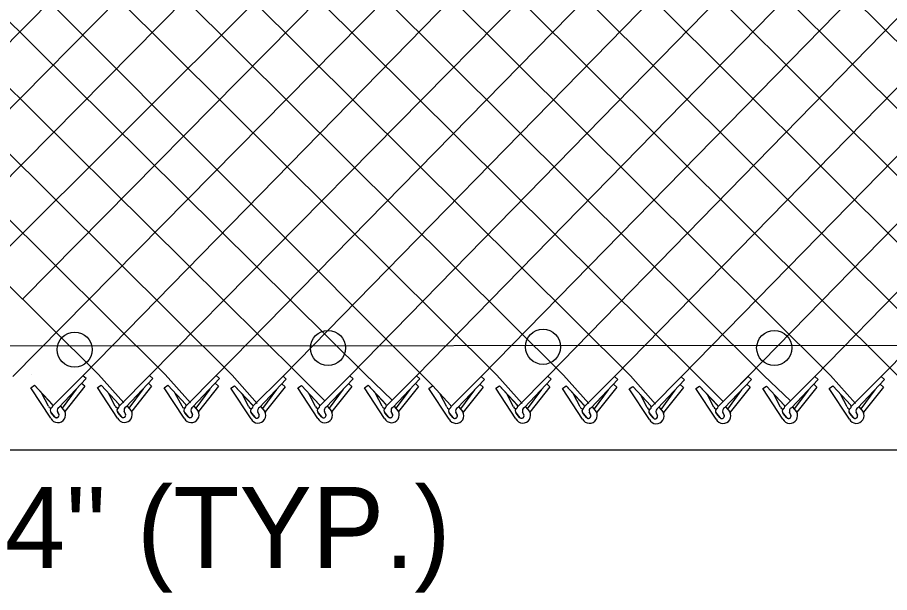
# Model space of a CAD drawing. Extents: x 0 to 1270, y 0 to 830.
# Drawn here: x 867.2 to 919.9, y 369.2 to 403.9 of the extents above; entities that cross this region are included whole.
import ezdxf

# ---------------------------------------------------------------- set-up
doc = ezdxf.new("R2010")
doc.units = 0
for name, color, linetype in [('CT_Dimensions', 7, 'Continuous'), ('sb_Chainlink Fence', 7, 'Continuous'), ('sb_Existing Structural Steel', 7, 'Continuous')]:
    doc.layers.add(name, color=color, linetype=linetype)

msp = doc.modelspace()

# ---------------------------------------------------------------- linework, layer by layer
at = {"layer": 'sb_Chainlink Fence'}
for p, q in [((816.414, 437.549), (872.125, 382.342)), ((836.532, 437.583), (892.288, 381.648)), ((840.607, 437.539), (896.164, 382.299)), ((844.66, 437.516), (900.191, 382.291)), ((848.65, 437.556), (904.222, 382.261)), ((852.704, 437.533), (908.25, 382.284)), ((856.741, 437.527), (912.277, 382.287)), ((860.842, 437.456), (916.291, 382.289)), ((865.54, 388.877), (914.406, 437.633)), ((850.828, 382.233), (904.801, 436.901)), ((915.349, 382.223), (968.936, 437.129)), ((866.942, 382.227), (920.625, 436.62)), ((867.562, 386.914), (916.354, 436.35)), ((871.171, 382.269), (924.083, 436.377)), ((874.065, 436.515), (928.376, 382.261)), ((879.224, 382.271), (932.156, 436.339)), ((883.256, 382.241), (936.183, 436.368)), ((887.284, 382.263), (940.214, 436.419)), ((891.31, 382.266), (944.243, 436.417)), ((895.209, 382.226), (948.269, 436.435)), ((899.236, 382.236), (952.075, 436.386)), ((903.263, 382.228), (956.31, 436.464)), ((907.294, 382.198), (960.337, 436.493)), ((910.415, 381.309), (964.368, 436.544)), ((919.363, 382.226), (972.423, 436.56)), ((846.789, 382.209), (900.235, 436.295)), ((854.855, 382.243), (908.301, 436.31)), ((822.448, 435.621), (876.152, 382.334)), ((826.475, 435.629), (880.184, 382.304)), ((834.503, 435.602), (888.238, 382.33)), ((866.918, 435.53), (920.318, 382.299)), ((870.946, 435.558), (924.345, 382.291)), ((879.005, 435.607), (932.405, 382.284)), ((883.031, 435.625), (936.431, 382.287)), ((887.046, 435.644), (940.47, 382.31)), ((875.197, 382.279), (926.633, 434.462)), ((832.366, 433.688), (884.212, 382.327)), ((868.099, 382.332), (868.099, 382.332)), ((869.357, 380.447), (871.171, 382.269)), ((871.368, 382.089), (871.171, 382.269)), ((872.125, 382.342), (873.643, 380.634)), ((873.384, 380.458), (875.197, 382.279)), ((875.395, 382.1), (875.197, 382.279)), ((876.152, 382.334), (877.67, 380.625)), ((877.411, 380.449), (879.224, 382.271)), ((879.422, 382.091), (879.224, 382.271)), ((880.184, 382.304), (881.701, 380.596)), ((881.442, 380.419), (883.256, 382.241)), ((883.454, 382.062), (883.256, 382.241)), ((884.212, 382.327), (885.783, 380.759)), ((885.47, 380.442), (887.284, 382.263)), ((887.482, 382.084), (887.284, 382.263)), ((888.238, 382.33), (889.844, 380.795)), ((889.497, 380.445), (891.31, 382.266)), ((891.508, 382.087), (891.31, 382.266)), ((893.395, 380.404), (895.209, 382.226)), ((895.407, 382.046), (895.209, 382.226)), ((896.164, 382.299), (897.681, 380.591)), ((897.422, 380.414), (899.236, 382.236)), ((899.433, 382.057), (899.236, 382.236)), ((900.191, 382.291), (901.708, 380.582)), ((901.449, 380.406), (903.263, 382.228)), ((903.461, 382.048), (903.263, 382.228)), ((904.222, 382.261), (905.74, 380.552)), ((905.48, 380.376), (907.294, 382.198)), ((907.492, 382.018), (907.294, 382.198)), ((908.25, 382.284), (909.821, 380.716)), ((909.509, 380.399), (911.322, 382.22)), ((911.52, 382.041), (911.322, 382.22)), ((912.277, 382.287), (913.882, 380.752)), ((913.535, 380.402), (915.349, 382.223)), ((915.547, 382.044), (915.349, 382.223)), ((916.291, 382.289), (917.809, 380.58)), ((917.55, 380.404), (919.363, 382.226)), ((919.561, 382.046), (919.363, 382.226)), ((868.027, 381.538), (868.25, 381.691)), ((868.25, 381.691), (869.328, 380.529)), ((868.25, 381.691), (869.334, 380.522)), ((869.756, 380.376), (871.368, 382.089)), ((871.301, 381.626), (870.095, 380.109)), ((871.301, 381.626), (871.103, 381.806)), ((872.053, 381.549), (872.276, 381.701)), ((872.276, 381.701), (873.354, 380.539)), ((872.276, 381.701), (873.361, 380.532)), ((873.782, 380.386), (875.395, 382.1)), ((875.328, 381.637), (874.122, 380.119)), ((875.328, 381.637), (875.13, 381.816)), ((876.08, 381.54), (876.303, 381.693)), ((876.303, 381.693), (877.381, 380.531)), ((876.303, 381.693), (877.388, 380.524)), ((877.81, 380.378), (879.422, 382.091)), ((879.355, 381.628), (878.149, 380.111)), ((879.355, 381.628), (879.157, 381.808)), ((880.112, 381.511), (880.335, 381.663)), ((880.335, 381.663), (881.413, 380.501)), ((880.335, 381.663), (881.42, 380.494)), ((881.841, 380.348), (883.454, 382.062)), ((883.386, 381.599), (882.18, 380.081)), ((883.386, 381.599), (883.188, 381.778)), ((884.14, 381.533), (884.363, 381.685)), ((884.363, 381.685), (885.441, 380.523)), ((884.363, 381.685), (885.448, 380.517)), ((885.869, 380.371), (887.482, 382.084)), ((887.415, 381.621), (886.208, 380.104)), ((887.415, 381.621), (887.217, 381.8)), ((888.166, 381.536), (888.389, 381.688)), ((888.389, 381.688), (889.467, 380.526)), ((888.389, 381.688), (889.474, 380.519)), ((889.896, 380.373), (891.508, 382.087)), ((891.441, 381.624), (890.235, 380.106)), ((891.441, 381.624), (891.243, 381.803)), ((892.062, 381.503), (892.285, 381.656)), ((892.288, 381.648), (893.366, 380.486)), ((892.288, 381.648), (893.373, 380.479)), ((893.794, 380.333), (895.407, 382.046)), ((895.34, 381.583), (895.142, 381.763)), ((896.092, 381.506), (896.315, 381.658)), ((896.315, 381.658), (897.393, 380.496)), ((896.315, 381.658), (897.399, 380.489)), ((897.821, 380.343), (899.433, 382.057)), ((899.366, 381.594), (898.16, 380.076)), ((899.366, 381.594), (899.168, 381.773)), ((900.119, 381.497), (900.342, 381.65)), ((900.342, 381.65), (901.42, 380.488)), ((900.342, 381.65), (901.427, 380.481)), ((901.848, 380.335), (903.461, 382.048)), ((903.393, 381.585), (903.196, 381.765)), ((904.15, 381.467), (904.373, 381.62)), ((904.373, 381.62), (905.451, 380.458)), ((904.373, 381.62), (905.458, 380.451)), ((905.879, 380.305), (907.492, 382.018)), ((907.425, 381.555), (907.227, 381.735)), ((908.178, 381.49), (908.401, 381.642)), ((908.401, 381.642), (909.479, 380.48)), ((908.401, 381.642), (909.486, 380.474)), ((909.907, 380.328), (911.52, 382.041)), ((911.453, 381.578), (911.255, 381.757)), ((912.205, 381.493), (912.428, 381.645)), ((912.428, 381.645), (913.506, 380.483)), ((912.428, 381.645), (913.513, 380.476)), ((913.934, 380.33), (915.547, 382.044)), ((915.479, 381.581), (915.282, 381.76)), ((916.219, 381.495), (916.442, 381.648)), ((916.442, 381.648), (917.52, 380.486)), ((916.442, 381.648), (917.527, 380.479)), ((917.948, 380.333), (919.561, 382.046)), ((919.494, 381.583), (919.296, 381.763)), ((869.245, 379.694), (868.027, 381.538)), ((869.106, 380.422), (868.7, 381.198)), ((870.782, 381.46), (869.933, 380.305)), ((873.272, 379.704), (872.053, 381.549)), ((873.133, 380.432), (872.727, 381.208)), ((874.809, 381.471), (873.96, 380.316)), ((877.299, 379.696), (876.08, 381.54)), ((877.16, 380.424), (876.754, 381.199)), ((878.836, 381.462), (877.987, 380.307)), ((881.33, 379.666), (880.112, 381.511)), ((881.191, 380.394), (880.785, 381.17)), ((882.867, 381.432), (882.018, 380.278)), ((885.358, 379.688), (884.14, 381.533)), ((885.22, 380.416), (884.814, 381.192)), ((886.895, 381.455), (886.047, 380.3)), ((889.385, 379.691), (888.166, 381.536)), ((889.246, 380.419), (888.84, 381.195)), ((890.922, 381.458), (890.073, 380.303)), ((893.283, 379.651), (892.065, 381.495)), ((893.144, 380.379), (892.739, 381.154)), ((894.82, 381.417), (893.972, 380.262)), ((895.34, 381.583), (894.133, 380.066)), ((897.31, 379.661), (896.092, 381.506)), ((897.171, 380.389), (896.765, 381.165)), ((898.847, 381.428), (897.998, 380.273)), ((901.337, 379.653), (900.119, 381.497)), ((901.198, 380.381), (900.792, 381.156)), ((902.874, 381.419), (902.025, 380.264)), ((903.393, 381.585), (902.187, 380.068)), ((905.368, 379.623), (904.15, 381.467)), ((905.229, 380.351), (904.824, 381.127)), ((906.905, 381.389), (906.057, 380.234)), ((907.425, 381.555), (906.218, 380.038)), ((909.396, 379.645), (908.178, 381.49)), ((909.258, 380.373), (908.852, 381.149)), ((910.934, 381.412), (910.085, 380.257)), ((911.453, 381.578), (910.247, 380.06)), ((913.423, 379.648), (912.205, 381.493)), ((913.284, 380.376), (912.878, 381.152)), ((914.96, 381.415), (914.111, 380.26)), ((915.479, 381.581), (914.273, 380.063)), ((917.437, 379.651), (916.219, 381.495)), ((917.299, 380.379), (916.893, 381.154)), ((918.974, 381.417), (918.126, 380.262)), ((919.494, 381.583), (918.288, 380.066)), ((869.471, 379.786), (869.269, 380.028)), ((869.269, 380.028), (869.491, 379.765)), ((869.732, 379.929), (869.65, 380.106)), ((869.65, 380.1), (869.731, 379.933)), ((869.823, 380.424), (870.071, 380.131)), ((869.827, 380.419), (870.072, 380.13)), ((870.071, 380.131), (870.089, 380.097)), ((870.089, 380.097), (870.105, 380.06)), ((873.497, 379.797), (873.295, 380.039)), ((873.295, 380.039), (873.518, 379.775)), ((873.758, 379.939), (873.677, 380.117)), ((873.677, 380.11), (873.758, 379.943)), ((873.85, 380.434), (874.098, 380.141)), ((873.853, 380.43), (874.099, 380.14)), ((874.098, 380.141), (874.116, 380.107)), ((874.116, 380.107), (874.131, 380.071)), ((877.524, 379.788), (877.322, 380.03)), ((877.322, 380.03), (877.545, 379.767)), ((877.786, 379.931), (877.704, 380.108)), ((877.704, 380.102), (877.785, 379.935)), ((877.877, 380.426), (878.125, 380.133)), ((877.88, 380.421), (878.126, 380.132)), ((878.125, 380.133), (878.143, 380.099)), ((878.143, 380.099), (878.159, 380.062)), ((881.817, 379.901), (881.735, 380.079)), ((881.735, 380.072), (881.817, 379.905)), ((881.908, 380.396), (882.156, 380.103)), ((881.912, 380.392), (882.157, 380.102)), ((882.156, 380.103), (882.174, 380.069)), ((882.174, 380.069), (882.19, 380.032)), ((885.584, 379.781), (885.382, 380.023)), ((885.382, 380.023), (885.605, 379.759)), ((885.845, 379.924), (885.763, 380.101)), ((885.764, 380.095), (885.845, 379.928)), ((885.937, 380.418), (886.184, 380.125)), ((885.94, 380.414), (886.186, 380.124)), ((886.184, 380.125), (886.203, 380.091)), ((886.203, 380.091), (886.218, 380.055)), ((889.61, 379.784), (889.408, 380.026)), ((889.408, 380.026), (889.631, 379.762)), ((889.872, 379.927), (889.79, 380.104)), ((889.79, 380.097), (889.871, 379.931)), ((889.963, 380.421), (890.211, 380.128)), ((889.966, 380.417), (890.212, 380.127)), ((890.211, 380.128), (890.229, 380.094)), ((890.229, 380.094), (890.245, 380.058)), ((893.77, 379.886), (893.688, 380.063)), ((893.688, 380.057), (893.77, 379.89)), ((893.862, 380.381), (894.109, 380.088)), ((893.865, 380.376), (894.11, 380.087)), ((894.109, 380.088), (894.127, 380.054)), ((894.127, 380.054), (894.143, 380.017)), ((897.797, 379.896), (897.715, 380.074)), ((897.715, 380.067), (897.796, 379.9)), ((897.888, 380.391), (898.136, 380.098)), ((897.892, 380.387), (898.137, 380.097)), ((898.136, 380.098), (898.154, 380.064)), ((898.154, 380.064), (898.17, 380.027)), ((901.824, 379.888), (901.742, 380.065)), ((901.742, 380.059), (901.824, 379.892)), ((901.915, 380.383), (902.163, 380.09)), ((901.919, 380.378), (902.164, 380.089)), ((902.163, 380.09), (902.181, 380.056)), ((902.181, 380.056), (902.197, 380.019)), ((905.855, 379.858), (905.773, 380.035)), ((905.774, 380.029), (905.855, 379.862)), ((905.947, 380.353), (906.194, 380.06)), ((905.95, 380.348), (906.196, 380.059)), ((906.194, 380.06), (906.212, 380.026)), ((906.212, 380.026), (906.228, 379.989)), ((909.883, 379.881), (909.802, 380.058)), ((909.802, 380.052), (909.883, 379.885)), ((909.975, 380.375), (910.223, 380.082)), ((909.978, 380.371), (910.224, 380.081)), ((910.223, 380.082), (910.241, 380.048)), ((910.241, 380.048), (910.256, 380.012)), ((913.91, 379.884), (913.828, 380.061)), ((913.828, 380.054), (913.91, 379.888)), ((914.001, 380.378), (914.249, 380.085)), ((914.005, 380.374), (914.25, 380.084)), ((914.249, 380.085), (914.267, 380.051)), ((914.267, 380.051), (914.283, 380.015)), ((917.924, 379.886), (917.843, 380.063)), ((917.843, 380.057), (917.924, 379.89)), ((918.016, 380.381), (918.264, 380.088)), ((918.019, 380.376), (918.265, 380.087)), ((918.264, 380.088), (918.282, 380.054)), ((918.282, 380.054), (918.297, 380.017)), ((881.556, 379.759), (881.354, 380)), ((881.354, 380), (881.576, 379.737)), ((893.509, 379.743), (893.307, 379.985)), ((893.307, 379.985), (893.529, 379.722)), ((897.536, 379.754), (897.334, 379.996)), ((897.334, 379.996), (897.556, 379.732)), ((901.563, 379.745), (901.361, 379.987)), ((901.361, 379.987), (901.583, 379.724)), ((905.594, 379.716), (905.392, 379.957)), ((905.392, 379.957), (905.614, 379.694)), ((909.622, 379.738), (909.42, 379.98)), ((909.42, 379.98), (909.643, 379.716)), ((913.649, 379.741), (913.447, 379.983)), ((913.447, 379.983), (913.669, 379.719)), ((917.663, 379.743), (917.461, 379.985)), ((917.461, 379.985), (917.684, 379.722)), ((832.127, 377.79), (1115.545, 377.765))]:
    msp.add_line(p, q, dxfattribs=at)
for centre, radius, start, end in [((869.232, 380.444), 0.128, 189.9304, 40.9785), ((869.398, 380.17), 0.192, 126.9947, 219.7983), ((869.404, 380.17), 0.195, 127.7656, 226.3328), ((869.664, 379.901), 0.468, 206.3202, 29.2269), ((869.844, 380.186), 0.209, 114.8422, 203.5167), ((873.259, 380.454), 0.128, 189.9304, 40.9785), ((873.425, 380.18), 0.192, 126.9947, 219.7983), ((873.43, 380.18), 0.195, 127.7656, 226.3328), ((873.691, 379.912), 0.468, 206.3202, 29.2269), ((873.87, 380.196), 0.209, 114.8422, 203.5167), ((877.286, 380.446), 0.128, 189.9304, 40.9785), ((877.452, 380.172), 0.192, 126.9947, 219.7983), ((877.457, 380.172), 0.195, 127.7656, 226.3328), ((877.718, 379.903), 0.468, 206.3202, 29.2269), ((877.898, 380.188), 0.209, 114.8422, 203.5167), ((881.317, 380.416), 0.128, 189.9304, 40.9785), ((881.483, 380.142), 0.192, 126.9947, 219.7983), ((881.489, 380.142), 0.195, 127.7656, 226.3328), ((881.749, 379.873), 0.468, 206.3202, 29.2269), ((881.929, 380.158), 0.209, 114.8422, 203.5167), ((885.346, 380.438), 0.128, 189.9304, 40.9785), ((885.512, 380.165), 0.192, 126.9947, 219.7983), ((885.517, 380.164), 0.195, 127.7656, 226.3328), ((885.777, 379.896), 0.468, 206.3202, 29.2269), ((885.957, 380.181), 0.209, 114.8422, 203.5167), ((889.372, 380.441), 0.128, 189.9304, 40.9785), ((889.538, 380.167), 0.192, 126.9947, 219.7983), ((889.543, 380.167), 0.195, 127.7656, 226.3328), ((889.804, 379.899), 0.468, 206.3202, 29.2269), ((889.984, 380.183), 0.209, 114.8422, 203.5167), ((893.27, 380.401), 0.128, 189.9304, 40.9785), ((893.437, 380.127), 0.192, 126.9947, 219.7983), ((893.442, 380.127), 0.195, 127.7656, 226.3328), ((893.702, 379.858), 0.468, 206.3202, 29.2269), ((893.882, 380.143), 0.209, 114.8422, 203.5167), ((897.297, 380.411), 0.128, 189.9304, 40.9785), ((897.463, 380.137), 0.192, 126.9947, 219.7983), ((897.469, 380.137), 0.195, 127.7656, 226.3328), ((897.729, 379.869), 0.468, 206.3202, 29.2269), ((897.909, 380.153), 0.209, 114.8422, 203.5167), ((901.324, 380.403), 0.128, 189.9304, 40.9785), ((901.49, 380.129), 0.192, 126.9947, 219.7983), ((901.496, 380.129), 0.195, 127.7656, 226.3328), ((901.756, 379.86), 0.468, 206.3202, 29.2269), ((901.936, 380.145), 0.209, 114.8422, 203.5167), ((905.355, 380.373), 0.128, 189.9304, 40.9785), ((905.522, 380.099), 0.192, 126.9947, 219.7983), ((905.527, 380.099), 0.195, 127.7656, 226.3328), ((905.787, 379.83), 0.468, 206.3202, 29.2269), ((905.967, 380.115), 0.209, 114.8422, 203.5167), ((909.384, 380.395), 0.128, 189.9304, 40.9785), ((909.55, 380.121), 0.192, 126.9947, 219.7983), ((909.555, 380.121), 0.195, 127.7656, 226.3328), ((909.816, 379.853), 0.468, 206.3202, 29.2269), ((909.995, 380.137), 0.209, 114.8422, 203.5167), ((913.41, 380.398), 0.128, 189.9304, 40.9785), ((913.576, 380.124), 0.192, 126.9947, 219.7983), ((913.582, 380.124), 0.195, 127.7656, 226.3328), ((913.842, 379.856), 0.468, 206.3202, 29.2269), ((914.022, 380.14), 0.209, 114.8422, 203.5167), ((917.425, 380.401), 0.128, 189.9304, 40.9785), ((917.591, 380.127), 0.192, 126.9947, 219.7983), ((917.596, 380.127), 0.195, 127.7656, 226.3328), ((917.857, 379.858), 0.468, 206.3202, 29.2269), ((918.036, 380.143), 0.209, 114.8422, 203.5167), ((869.587, 379.884), 0.152, 219.8632, 17.4852), ((869.588, 379.883), 0.152, 230.7826, 19.2656), ((873.614, 379.894), 0.152, 219.8632, 17.4852), ((873.614, 379.893), 0.152, 230.7826, 19.2656), ((877.641, 379.886), 0.152, 219.8632, 17.4852), ((877.641, 379.885), 0.152, 230.7826, 19.2656), ((881.672, 379.856), 0.152, 219.8632, 17.4852), ((881.673, 379.855), 0.152, 230.7826, 19.2656), ((885.7, 379.878), 0.152, 219.8632, 17.4852), ((885.701, 379.877), 0.152, 230.7826, 19.2656), ((889.727, 379.881), 0.152, 219.8632, 17.4852), ((889.727, 379.88), 0.152, 230.7826, 19.2656), ((893.625, 379.841), 0.152, 219.8632, 17.4852), ((893.626, 379.84), 0.152, 230.7826, 19.2656), ((897.652, 379.851), 0.152, 219.8632, 17.4852), ((897.653, 379.85), 0.152, 230.7826, 19.2656), ((901.679, 379.843), 0.152, 219.8632, 17.4852), ((901.68, 379.842), 0.152, 230.7826, 19.2656), ((905.71, 379.813), 0.152, 219.8632, 17.4852), ((905.711, 379.812), 0.152, 230.7826, 19.2656), ((909.739, 379.835), 0.152, 219.8632, 17.4852), ((909.739, 379.834), 0.152, 230.7826, 19.2656), ((913.765, 379.838), 0.152, 219.8632, 17.4852), ((913.766, 379.837), 0.152, 230.7826, 19.2656), ((917.78, 379.841), 0.152, 219.8632, 17.4852), ((917.78, 379.84), 0.152, 230.7826, 19.2656)]:
    msp.add_arc(centre, radius, start, end, dxfattribs=at)
at = {"layer": 'sb_Existing Structural Steel'}
msp.add_line((440.979, 383.869), (1116.811, 384.201), dxfattribs=at)
for centre in [(870.683, 383.845), (885.971, 383.943), (898.951, 384.012), (912.9, 383.94)]:
    msp.add_circle(centre, 1.06, dxfattribs=at)

# ---------------------------------------------------------------- texts
at = {"layer": 'CT_Dimensions'}
msp.add_text("4'' (TYP.)", height=4.9005, rotation=360, dxfattribs=at).set_placement((866.473, 370.65))

doc.saveas('drawing.dxf')
